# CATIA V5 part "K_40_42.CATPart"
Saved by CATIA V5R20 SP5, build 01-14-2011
Part number: 40_42
Bounding box of the stored display mesh (mm): x -150 to 150, y -25 to 170, z 0 to 20
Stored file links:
  G:\Khaled_CFAO_2011\ST2M\ST2M_GR1\lpierredon\Khaled\CAD_thinkMOTION\K_40_42.CATPart
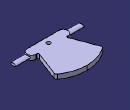
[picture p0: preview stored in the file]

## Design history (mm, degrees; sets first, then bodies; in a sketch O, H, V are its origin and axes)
Set1
  Plane1: type Offset, RefPlane yz-plane, Offset 150
Body1 (main body)
  Sketch1 on xy-plane, origin (0, 0, 0), H (1, 0, 0), V (0, 1, 0)
    arc A1 centre (0, 0) radius 170 from (0, 170) to (-105.2557, 133.4962) ccw
    point P1 (0, 170)
    point P2 (0, -25)
    line L1 (0, -25) -> (-70, -25)
    point P3 (-70, -25)
    arc A2 centre (-70, -5) radius 20 from (-70, 15) to (-70, -25) ccw
    point P5 (-50.6351, 0)
    line L2 (-70, 15) -> (-60, 15)
    point P6 (-70, 15)
    point P7 (-60, 15)
    line L3 (-60, 15) -> (-105.2557, 133.4962)
    point P8 (-105.2557, 133.4962)
    point P9 (0, 0)
    construction line L4 through (0, 0) direction (-1, 0)
    point P10 (0, 170)
    point P11 (0, -25)
    point P12 (70, -25)
    point P14 (50.6351, 0)
    point P15 (70, 15)
    point P16 (60, 15)
    point P17 (105.2557, 133.4962)
    arc A3 centre (0, 0) radius 170 from (0, 170) to (105.2557, 133.4962) cw
    line L5 (0, -25) -> (70, -25)
    arc A4 centre (70, -5) radius 20 from (70, 15) to (70, -25) cw
    line L6 (70, 15) -> (60, 15)
    line L7 (60, 15) -> (105.2557, 133.4962)
    radius A1 = 170
    length L1 = 70
    radius A2 = 20
    length L2 = 10
    distance O P2 = 25
    horizontal: L1 H, L2 H
    tangency: A2 L1, L2 A2
    coincidence: A2 P5, P5 H, O P9, P1 P10, P2 P11
    symmetry: H L4 V, P1 P10 V, P2 P11 V, P3 P12 V, P5 P14 V, P6 P15 V, P7 P16 V, P8 P17 V, A1 A3 V, L1 L5 V, A2 A4 V, L2 L6 V, L3 L7 V
  Pad1: profile Sketch1, direction (0, 0, 1), length 20
  Fillet1: radius 10, on edge [face of Pad1 from Sketch1.L3 | face of Pad1 from Sketch1.A1]; edge [face of Pad1 from Sketch1.A3 | face of Pad1 from Sketch1.L7]
  Fillet2: radius 5, on edge [face of Pad1 from Sketch1.L7 | face of Pad1 from Sketch1.L6]; edge [face of Pad1 from Sketch1.L2 | face of Pad1 from Sketch1.L3]
  Sketch2 on end face of Pad1, origin (-15.4691, 14.6089, 20), H (1, 0, 0), V (0, 1, 0)
    point P1 (15.4691, -14.6089)
    reference intersected line E1 through (15.4691, 0) direction (0, 1) from yz-plane
    reference intersected line E2 through (0, -14.6089) direction (-1, 0) from zx-plane
    coincidence: P1 E1, P1 E2
  Hole1: placed by Sketch2, at (0, 0, 20) direction (0, 0, -1), diameter 16, through (limit type 6)
  Sketch3 on Plane1, origin (150, 0, 0), H (0, 1, 0), V (0, 0, 1)
    point P1 (-5, 10)
    ellipse A1 centre (-5, 10) semi-axes 12.5, 5 rotation 0
    point P2 (0, 14.5826)
    reference projected line E1 (-25, 0) -> (-25, 20) from edge [face of Pad1 from Sketch1.A4 | face of Pad1 from Sketch1.L5]
    distance P1 H = 10
    distance P1 E1 = 20
    "Radius" A1 = 12.5
    "Radius" A1 = 12.5 (reference)
    coincidence: P2 V, A1 P2
  Pad2: profile Sketch3, direction (-1, 0, 0), up to the existing solid (limit type 2)
  Mirror1: of Pad2, Sketch3, about yz-plane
